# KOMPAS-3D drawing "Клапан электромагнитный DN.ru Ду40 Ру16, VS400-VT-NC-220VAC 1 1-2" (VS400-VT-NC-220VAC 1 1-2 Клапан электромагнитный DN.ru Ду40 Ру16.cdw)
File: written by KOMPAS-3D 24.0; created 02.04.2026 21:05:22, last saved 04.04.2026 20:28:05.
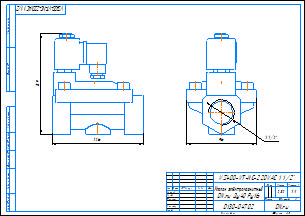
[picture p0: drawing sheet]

Document properties: c3d_UniqueCompID: ef56311e-7521-43dc-8291-0e6108b3d81d; Обозначение: VS400-ET-NC-220VAC 1; Наименование: Клапан электромагнитный DN.ru Ду25 Ру16; Автор: artio; Класс точности: c; Знак неуказанной шероховатости: Шероховатость не задана; Рассекать на разрезах: Да; c3d_UniqueCompID: ef56311e-7521-43dc-8291-0e6108b3d81d; Обозначение: VS400-ET-NC-220VAC 1-2; Наименование: Клапан электромагнитный DN.ru Ду15 Ру16; Автор: artio; Класс точности: c; Знак неуказанной шероховатости: Шероховатость не задана; Рассекать на разрезах: Да; c3d_UniqueCompID: ef56311e-7521-43dc-8291-0e6108b3d81d; Обозначение: VS400-ET-NC-220VAC 3-4; Наименование: Клапан электромагнитный DN.ru Ду20 Ру16; Автор: artio; Класс точности: c; Знак неуказанной шероховатости: Шероховатость не задана; Рассекать на разрезах: Да; c3d_UniqueCompID: ef56311e-7521-43dc-8291-0e6108b3d81d; Обозначение: VS400-ET-NC-220VAC 1 1-4; Наименование: Клапан электромагнитный DN.ru Ду32 Ру16; Автор: artio; Класс точности: c; Знак неуказанной шероховатости: Шероховатость не задана; Рассекать на разрезах: Да; c3d_UniqueCompID: ef56311e-7521-43dc-8291-0e6108b3d81d; Обозначение: VS400-ET-NC-220VAC 3-8; Наименование: Клапан электромагнитный DN.ru Ду10 Ру16; Автор: artio; Класс точности: c; Знак неуказанной шероховатости: Шероховатость не задана; Рассекать на разрезах: Да; c3d_UniqueCompID: ef56311e-7521-43dc-8291-0e6108b3d81d; Обозначение: VS400-ET-NC-220VAC 1 1-2; Наименование: Клапан электромагнитный DN.ru Ду40 Ру16; Автор: artio; Класс точности: c; Знак неуказанной шероховатости: Шероховатость не задана; Рассекать на разрезах: Да; Автор: artio; Форматы листов документа: A3; Полное имя файла: VS400-VT-NC-220VAC 1 1-2 Клапан электромагнитный DN.ru Ду40 Ру16.m3d; Масса: 2.321; Наименование: Клапан электромагнитный DN.ru Ду40 Ру16; Количество листов документа: 1; Примечание: D130-04702

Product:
- Body: Тело 1  | qty 1
    Масса: 4.144257
- Part/product: Клапан электромагнитный DN.ru Ду40 Ру16  | designation VS400-VT-NC-220VAC 1 1-2
    Масса: 2.321
    Раздел спецификации: Прочие изделия
    Примечание: D130-04702
    additional columns: ef56311e-7521-43dc-8291-0e6108b3d81d; VS400-ET-NC-220VAC 1 1-2; artio; c; Шероховатость не задана; Да

Views: Вид 1, Спереди
Referenced files in C:\Users\artio\OneDrive\Рабочий стол\Клапан электромагнитный DN.ru VS4x-xT-NC-x\DN10\: VS400-ET-NC-220VAC 3-8 Клапан электромагнитный DN.ru Ду10 Ру16.m3d, VS400-ET-NC-220VAC 3-8 Клапан электромагнитный DN.ru Ду10 Ру16.cdw
Referenced files in C:\Users\artio\OneDrive\Рабочий стол\Клапан электромагнитный DN.ru\VS400-VT-NC\VS400-VT-NC-220VAC\: VS400-VT-NC-220VAC 1 1-2 Клапан электромагнитный DN.ru Ду40 Ру16.m3d
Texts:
  VS400-VT-NC-220VAC 1 1-2
  Клапан электромагнитный
  DN.ru Ду40 Ру16
  VS400-VT-NC-220VAC 1 1/2"
  VS400-VT-NC-220VAC 1 1/2"-
  Клапан электромагнитный DN.ru Ду40 Ру16
  VS400-VT-NC-220VAC 1 1-2 Клапан электромагнитный DN.ru Ду40 Ру16
Dimensions and other numbers on the sheet: 0; 3; 2; 4; 96; 1 1/2"; 1:1; 1; 2,32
